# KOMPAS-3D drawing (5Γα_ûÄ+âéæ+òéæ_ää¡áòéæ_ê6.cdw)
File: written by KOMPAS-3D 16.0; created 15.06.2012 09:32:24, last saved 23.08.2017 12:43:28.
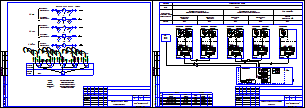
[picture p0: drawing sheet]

Sheets 1-2: A3, landscape

Title block, sheet 1: name: Руководство по эксплуатации; sheet number: 1; sheets: 27; organisation: ООО"Интелприбор"; sheet format: A3; stored path: W:\Users\smirnov_v\Desktop\шаблоны\4-х трубка\4-х трубка ГВС-max.cdw / D:\Проекты\Лыткарино\ул. Квартал 3А, д.25\710.74 РП.cdw; file name: 4-х трубка ГВС-max.cdw / 710.74 РП.cdw; cell 51: МО, Воскресенсикй р-н, п. Хорлово, ул. Интернациональная, д. 4; cell 320: Р
Title block, sheet 2: sheet number: 2

Views: Вид 2, Вид 3
Referenced files in C:\Program Files (x86)\ASCON\KOMPAS-3D V16\Sys\: spds.lcs, EngSys.lcs, GRAPHIC.LHS
Referenced files: graphic.tdp
Referenced files in W:\Users\smirnov_v\Desktop\шаблоны\4-х трубка\: 4-х трубка ГВС-max.cdw
Referenced files in D:\Проекты\Лыткарино\ул. Квартал 3А, д.25\: 710.74 РП.cdw
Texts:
  Смирнов В.С.
  УУ-3423
  GOST Common
  Normal
  List Paragraph
  heading 3
  для схемы
  txt
  Т0-элементы
  Плата подключений
  Агрегат
  Системный блок  МКТС
  Среда
  Вода
  параметра и место
  отбора импульса
  Учет тепловой энергии и
  теплоносителя системы отопления
  Подающий
  трубопровод
  отопления
  Обратный
  расхода горячей водысистемы ГВС
  Вводной
  трубопровод ХВС
  Узел учета ХВС
  ГВС
  ИМ1
  ИМ2
  ИМ3
  ИМ4
  ИМ5
  СБ МКТС
  ВРУ
  UP+
  UP-
  ИМП
  Лин
  Измерительный
  модуль М121
  Pt 100
  Преобразователь
  температуры
  давления
  каб.
  Начало
  трассы
  Трассы
  Марка
  Проложен
  Изм. модуль (Т1)
  Изм. модуль (Т2)
  Изм. модуль (Т3)
  Изм. модуль (Т4)
  Изм. модуль (В1)
  ВРУ 220В, 50 Гц
  ИМ (Т1)
  ИМ (Т3)
  FTP
  ПВС
  Конец
  Кол-во и
  сеч. жил
  Длина,
  приборы
  по месту
  шкаф
  учета
  UQIES
  Преобразователь расхода
  Термопреобразователь
  Преобразователь давления
  Преобразователь цифровой
  Системный блок МКТС
  Функциональная схема
  УУГВС
  УУТЭ
  УУХВС
  Размеры, параметризация
  сит. план
  подача ГВС
  обратка ГВС
  хвс
  обратка
  POLYLINE_STYLE_0.25_RGB_0_0_0
  стены
  Основная (не является границей для штриховки)
  POLYLINE_STYLE_0.18_RGB_0_0_0
  ХВС
  зеленая
  Красная тонкая
  арматура
  Подача
  Скрытая линия
  Ось Z
  Ось Y
  Ось X
  Образующая трубопровода (проектируемого)
  Трубопровод толщиной 0.6мм (одна линия)
  Трубопровод толщиной 1.2мм (одна линия)
  Трубопровод толщиной 1.0мм (одна линия)
  Трубопровод толщиной 0.8мм (одна линия)
  Трубопровод существующий (одна линия)
  Трубопровод невидимый (одна линия)
  Трубопровод демонтируемый (одна линия)
  Осевая трубопровода
  Осевая трубопровода (демонтируемого)
  Образующая трубопровода (существующего)
  Образующая трубопровода (невидимого)
  Изолированный трубопровод проектируемый (одна линия)
  Изолированный трубопровод существующий (одна линия)
  Образующая изоляции
  Изоляция
  Изолированный трубопровод невидимый (одна линия)
  Штрих пвс 075
  штрих пвс 2,5
  существующее оборудование
  Существующее оборудование
  K5LT_BASIC_RGB_0_0_255_THICK_0.53
  POLYLINE_STYLE_1.51_RGB_0_0_255
  POLYLINE_STYLE_0.50_RGB_128_128_128
  K5LT_AXLED_RGB_255_128_0_SC_1_THICK_0.18
  ACAD_ISO04W100_RGB_0_0_0_SC_1_THICK_0.18
  тонкая черная
  тонкая красная
  тонкая синяя
  тонкая оранж
  красн штрих
  пломбировка
  Провода
  синий штрих
  Стили документа
  G2co
  расход вторичной воды объемный
  расход вторичной воды объемный при 70гр
  Gco
  расход теплоносителя массовый
  расход теплоносит объемн подающ
  расход теплоносит объемн обр
  Лапир
  Ghvs
  Im1
  Im2
  Im3
  Im4
  Im5
  Khvs
  норматив ХВС
  число подъездов
  число этажей
  Nkv
  число квартир
  тепловая нагрузка на отопление
  сумма Q
  Qgvs
  тепловая нагрузка ГВС
  тепловая нагрузка на циркуляцию ГВС
  иммитовставка или под манометр
  ro1
  ro2
  ro3
  ro4
  верх предел темп граф
  нижн предел темп граф
  темп подачи ГВС
  темп обр ГВС
  темр хол воды
  vzdh
  Kchn
  Ktp
  Knp
  tnv
  Vклап
  KLP
  RPD
  RDS
  PUMP
  ro5
  beta
  tnv98
  Shifr
  Переход ГОСТ 17378-2001
  Переход
  ГОСТ
  Сталь 09Г2С ГОСТ 19281-89
  Втулка 20x50
  Лит-Масса-Масштаб
  Материал-Предприятие
  Title Specification
  Body Specification ( left align )
  Body Specificaton ( centered )
  Поз.
  Кол.
  Приме-
  чание
  Таблица спецификации
  Засыпка
  Штрих3
  Штрих2
  Штрих1
  Песок
  Штр0.5пр7
  Штр0.5пр12
  Штр0.3пр10
  Штр1.4пр21.21
  Штр1пр15
  Штр2.12пр35
  Штр1.5пр25
  Штр2.82пр42.42
  Штр2пр30
  SACNCR_ISO 1
  Электрощитовая
  Пр-1
  Ок-1
  Обозначение стандарта
  Типоразмер
  Пояснительная записка
  автоматизации
  Рабочие чертежи основного комплекта. ГОСТ Р 21.1101-2009 Ф3
  Стадия
  Лист
  Листов
  Изм.
  Кол.уч.
  №док.
  Подп.
  Дата
  Разраб.
  Пров.
  Т.контр.
  Н.контр.
  Утв.
  Изменение
  Номер документа
  Подпись
  Наименование объекта строительства, в состав которого входит здание, наим. микр
  Наименование здания (сооружения)
  Порядковый номер листа
  Количество листов в документе
  Наименование изображения
  Индекс предприятия, выпускающего документ
  Инв. № подл.
  Подп. и дата
  Взам. инв. №
  Инвентарный номер подлинника
  Подпись принявшего подлинник на хранение
  Инвентарный номер подлинника, взамен которого выпущен данный подлинник
  Согласовано
  Формат листа
  Согласование
  03 Рабочие чертежи основного комплекта. ГОСТ Р 21.1101-2009 Ф3
  Схема соединений внешних
  проводок
Dimensions and other numbers on the sheet: 1; 2; 3; 6; 5; 4; 220В; 50Гц; 4-20; 2x2x0,52; 3х0,75; 20; 11; 15; 16; 10; 7; 17; 0; 5,0; 3,2388; 0,0400; 40; 95; 3,1876; 4,5; 0,0; 0,0000; 70; 9; 12; 13; 14; 8; 18; 1,2,3,4,5; 6,7,8,9; 10,11,12,13,14; 15,16,17,18,19; 19; 09Г2С; 27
